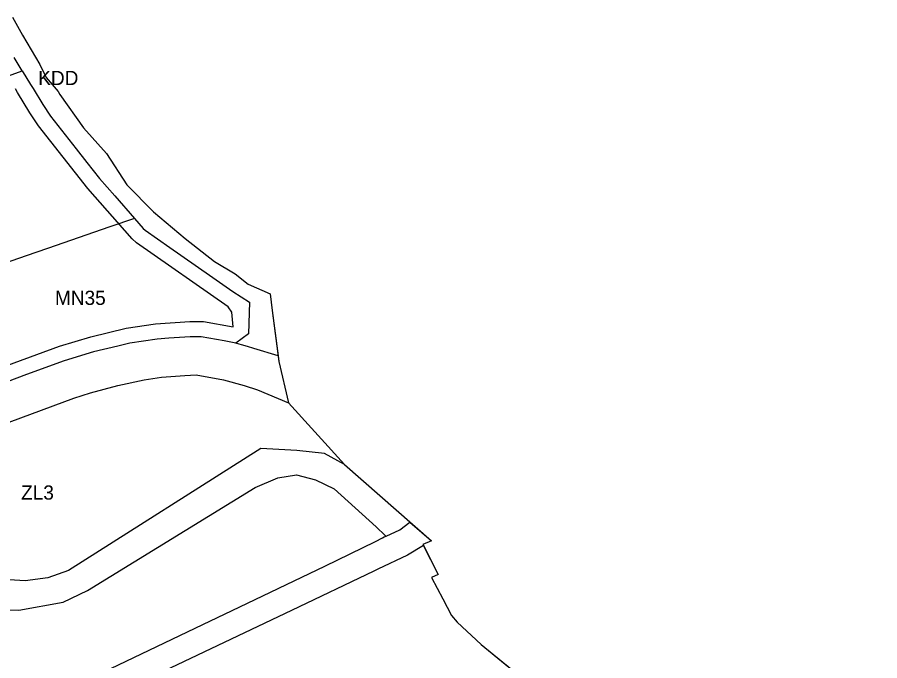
# Model space of a CAD drawing. Extents: x 7428103 to 7431580, y 5545880 to 5549002.
# Drawn here: x 7431185 to 7431521.6, y 5546633.5 to 5546884.5 of the extents above; entities that cross this region are included whole.
import ezdxf

# ---------------------------------------------------------------- set-up
doc = ezdxf.new("R2010")
doc.units = 0
for name, color, linetype in [('CZ_L_granica obszaru objętego planem', 7, 'Continuous'), ('CZ_L_linie rozgraniczające tereny o różnym przeznaczeniu oraz różnych warunkach ich zabudowy i zagospodarowania', 7, 'Continuous'), ('CZ_L_maksymalne nieprzekraczalne linie zabudowy', 7, 'Continuous'), ('CZ_L_opisy_linie rozgraniczające tereny o różnym przeznaczeniu oraz różnych warunkach ich zabudowy i zagospodarowania', 7, 'Continuous')]:
    doc.layers.add(name, color=color, linetype=linetype)

msp = doc.modelspace()

# ---------------------------------------------------------------- linework, layer by layer
at = {"layer": 'CZ_L_granica obszaru objętego planem'}
for p, q in [((7431183.18, 5546884.54), (7431187.05, 5546877.6)), ((7431187.05, 5546877.6), (7431193.79, 5546866.06)), ((7431193.79, 5546866.06), (7431196.35, 5546861.06)), ((7431196.35, 5546861.06), (7431200.97, 5546855.59)), ((7431200.97, 5546855.59), (7431201.59, 5546854.35)), ((7431201.59, 5546854.35), (7431210.87, 5546841.43)), ((7431210.87, 5546841.43), (7431219.91, 5546831.33)), ((7431219.91, 5546831.33), (7431227.79, 5546819.16)), ((7431227.79, 5546819.16), (7431238.16, 5546808.56)), ((7431238.16, 5546808.56), (7431250.54, 5546798.16)), ((7431250.54, 5546798.16), (7431262.01, 5546789.22)), ((7431262.01, 5546789.22), (7431270.01, 5546784.44)), ((7431270.01, 5546784.44), (7431275.18, 5546780.34)), ((7431275.18, 5546780.34), (7431283.69, 5546776.59)), ((7431283.69, 5546776.59), (7431284.51, 5546770.13)), ((7431284.51, 5546770.13), (7431287.06, 5546750.2)), ((7431287.06, 5546750.2), (7431290.91, 5546734.15)), ((7431290.91, 5546734.15), (7431312.74, 5546710.03)), ((7431312.74, 5546710.03), (7431346.63, 5546680.19)), ((7431346.63, 5546680.19), (7431343.34, 5546678.77)), ((7431343.34, 5546678.77), (7431349.21, 5546667.11)), ((7431349.21, 5546667.11), (7431346.72, 5546665.9)), ((7431346.72, 5546665.9), (7431351.03, 5546657.57)), ((7431351.03, 5546657.57), (7431354.43, 5546651.12)), ((7431354.43, 5546651.12), (7431356.66, 5546648.48)), ((7431356.66, 5546648.48), (7431366.02, 5546639.74)), ((7431366.02, 5546639.74), (7431478.6, 5546548.15))]:
    msp.add_line(p, q, dxfattribs=at)
at = {"layer": 'CZ_L_linie rozgraniczające tereny o różnym przeznaczeniu oraz różnych warunkach ich zabudowy i zagospodarowania'}
for p, q in [((7431187, 5546863.62), (7431183.87, 5546868.83)), ((7431178.79, 5546860.67), (7431187, 5546863.62)), ((7431187, 5546863.62), (7431190.18, 5546858.32)), ((7431190.18, 5546858.32), (7431190.24, 5546858.3)), ((7431190.24, 5546858.3), (7431191.21, 5546856.71)), ((7431191.21, 5546856.71), (7431195.05, 5546850.47)), ((7431195.05, 5546850.47), (7431197.97, 5546845.99)), ((7431197.97, 5546845.99), (7431207.97, 5546833.17)), ((7431207.97, 5546833.17), (7431212.2, 5546827.84)), ((7431212.2, 5546827.84), (7431217.15, 5546821.64)), ((7431217.15, 5546821.64), (7431223.05, 5546814.81)), ((7431223.05, 5546814.81), (7431230.79, 5546805.96)), ((7431230.79, 5546805.96), (7431221.12, 5546802.73)), ((7431221.12, 5546802.73), (7431196.77, 5546794.37)), ((7431196.77, 5546794.37), (7431188.57, 5546791.51)), ((7431188.57, 5546791.51), (7431169.17, 5546784.73)), ((7431228.92, 5546757.36), (7431224.25, 5546756.25)), ((7431239.65, 5546758.98), (7431228.92, 5546757.36)), ((7431244.21, 5546759.35), (7431239.65, 5546758.98)), ((7431252.46, 5546759.87), (7431244.21, 5546759.35)), ((7431256.85, 5546759.86), (7431252.46, 5546759.87)), ((7431265.73, 5546758.32), (7431256.85, 5546759.86)), ((7431269.73, 5546757.52), (7431265.73, 5546758.32)), ((7431270.37, 5546757.34), (7431269.73, 5546757.52)), ((7431271.65, 5546756.96), (7431270.37, 5546757.34)), ((7431214.83, 5546753.96), (7431203.28, 5546750.43)), ((7431224.25, 5546756.25), (7431214.83, 5546753.96)), ((7431272.57, 5546756.69), (7431271.65, 5546756.96)), ((7431274.86, 5546756.03), (7431272.57, 5546756.69)), ((7431274.87, 5546756.04), (7431274.86, 5546756.03)), ((7431274.88, 5546756.02), (7431274.87, 5546756.04)), ((7431277.34, 5546755.27), (7431274.88, 5546756.02)), ((7431286.78, 5546752.37), (7431277.34, 5546755.27)), ((7431203.28, 5546750.43), (7431188.68, 5546745.1)), ((7431188.68, 5546745.1), (7431174.41, 5546739.84)), ((7431234.49, 5546743.11), (7431241.27, 5546744.14)), ((7431241.27, 5546744.14), (7431250.46, 5546744.72)), ((7431250.46, 5546744.72), (7431254.85, 5546744.99)), ((7431254.85, 5546744.99), (7431265.53, 5546743.12)), ((7431213.57, 5546737.95), (7431224.28, 5546740.87)), ((7431224.28, 5546740.87), (7431234.49, 5546743.11)), ((7431265.53, 5546743.12), (7431273.53, 5546740.79)), ((7431273.53, 5546740.79), (7431278.75, 5546739.17)), ((7431207.14, 5546735.92), (7431213.57, 5546737.95)), ((7431278.75, 5546739.17), (7431290.91, 5546734.15)), ((7431186.42, 5546728.28), (7431207.14, 5546735.92)), ((7431168.64, 5546721.72), (7431186.42, 5546728.28)), ((7431280.13, 5546716.3), (7431205.02, 5546668.68)), ((7431294.15, 5546715.44), (7431280.13, 5546716.3)), ((7431304.94, 5546714.29), (7431294.15, 5546715.44)), ((7431312.74, 5546710.03), (7431304.94, 5546714.29)), ((7431277.83, 5546701.12), (7431286.65, 5546704.81)), ((7431286.65, 5546704.81), (7431294.04, 5546706.01)), ((7431294.04, 5546706.01), (7431301.39, 5546704.08)), ((7431301.39, 5546704.08), (7431308.67, 5546700.47)), ((7431212.38, 5546660.92), (7431277.83, 5546701.12)), ((7431308.67, 5546700.47), (7431325.05, 5546685.68)), ((7431334.27, 5546684.54), (7431338.27, 5546687.56)), ((7431325.05, 5546685.68), (7431325.04, 5546685.67)), ((7431325.04, 5546685.67), (7431328.61, 5546682.38)), ((7431329, 5546682.06), (7431334.27, 5546684.54)), ((7431305.06, 5546670.35), (7431324.83, 5546680)), ((7431324.83, 5546680), (7431327.58, 5546681.48)), ((7431327.58, 5546681.48), (7431328.25, 5546681.84)), ((7431328.25, 5546681.84), (7431329, 5546682.06)), ((7431328.61, 5546682.38), (7431329, 5546682.06)), ((7431343.49, 5546678.46), (7431337.27, 5546674.65)), ((7431337.27, 5546674.65), (7431325.71, 5546669.15)), ((7431268.87, 5546653.06), (7431305.06, 5546670.35)), ((7431205.02, 5546668.68), (7431196.91, 5546665.81)), ((7431324.12, 5546668.4), (7431292, 5546653.12)), ((7431325.71, 5546669.15), (7431324.12, 5546668.4)), ((7431188.16, 5546664.65), (7431177.42, 5546665.27)), ((7431196.91, 5546665.81), (7431188.16, 5546664.65)), ((7431203, 5546656.37), (7431212.38, 5546660.92)), ((7431185.7, 5546653.13), (7431203, 5546656.37)), ((7431176.99, 5546653.49), (7431185.7, 5546653.13)), ((7431292, 5546653.12), (7431226.3, 5546621.87)), ((7431257.48, 5546647.63), (7431268.87, 5546653.06)), ((7431218.59, 5546629.03), (7431257.48, 5546647.63))]:
    msp.add_line(p, q, dxfattribs=at)
for points in [[(7431183.18, 5546884.54), (7431187.05, 5546877.6), (7431193.79, 5546866.06), (7431196.35, 5546861.06), (7431200.97, 5546855.59), (7431201.59, 5546854.35), (7431210.87, 5546841.43), (7431219.91, 5546831.33), (7431227.79, 5546819.16), (7431238.16, 5546808.56), (7431250.54, 5546798.16), (7431262.01, 5546789.22), (7431270.01, 5546784.44), (7431275.18, 5546780.34), (7431283.69, 5546776.59), (7431284.51, 5546770.13), (7431286.78, 5546752.37)], [(7431230.79, 5546805.96), (7431230.79, 5546805.96)], [(7431230.79, 5546805.96), (7431234.22, 5546802.16), (7431234.96, 5546801.42), (7431244.56, 5546794.68), (7431259.98, 5546783.96), (7431269.17, 5546777.54), (7431275.64, 5546773.42), (7431275.25, 5546761.05), (7431270.37, 5546757.34)], [(7431286.78, 5546752.37), (7431287.06, 5546750.2), (7431290.91, 5546734.15)], [(7431290.91, 5546734.15), (7431312.74, 5546710.03)], [(7431312.74, 5546710.03), (7431338.27, 5546687.56)], [(7431338.27, 5546687.56), (7431346.63, 5546680.19), (7431343.34, 5546678.77), (7431343.49, 5546678.46)], [(7431343.49, 5546678.46), (7431349.21, 5546667.11), (7431346.72, 5546665.9), (7431351.03, 5546657.57), (7431354.43, 5546651.12), (7431356.66, 5546648.48), (7431366.02, 5546639.74), (7431478.6, 5546548.15), (7431499.55, 5546531.09), (7431503.69, 5546527.66), (7431504.5, 5546526.92), (7431509.59, 5546522.35), (7431519.5, 5546513.29), (7431521.58, 5546512.74)]]:
    msp.add_lwpolyline(points, dxfattribs=at)
at = {"layer": 'CZ_L_maksymalne nieprzekraczalne linie zabudowy'}
msp.add_lwpolyline([(7431141.98, 5546734.3), (7431201.48, 5546756.15), (7431213.71, 5546759.85), (7431227.5, 5546763.18), (7431238.99, 5546764.95), (7431252.37, 5546765.87), (7431257.66, 5546765.8), (7431269.33, 5546763.72), (7431268.74, 5546769.43), (7431267.3, 5546771.6), (7431231.51, 5546796.51), (7431229.84, 5546798.06), (7431212.56, 5546817.77), (7431193.31, 5546842.22), (7431189.98, 5546847.26), (7431185.11, 5546855.13), (7431184.36, 5546856.6)], dxfattribs=at)

# ---------------------------------------------------------------- texts
at = {"layer": 'CZ_L_opisy_linie rozgraniczające tereny o różnym przeznaczeniu oraz różnych warunkach ich zabudowy i zagospodarowania'}
for s, p in [('KDD', (7431193.22, 5546858.07)), ('MN35', (7431199.75, 5546772.29)), ('ZL3', (7431186.53, 5546696.32))]:
    msp.add_text(s, height=5.549, dxfattribs=at).set_placement(p)

doc.saveas('drawing.dxf')
